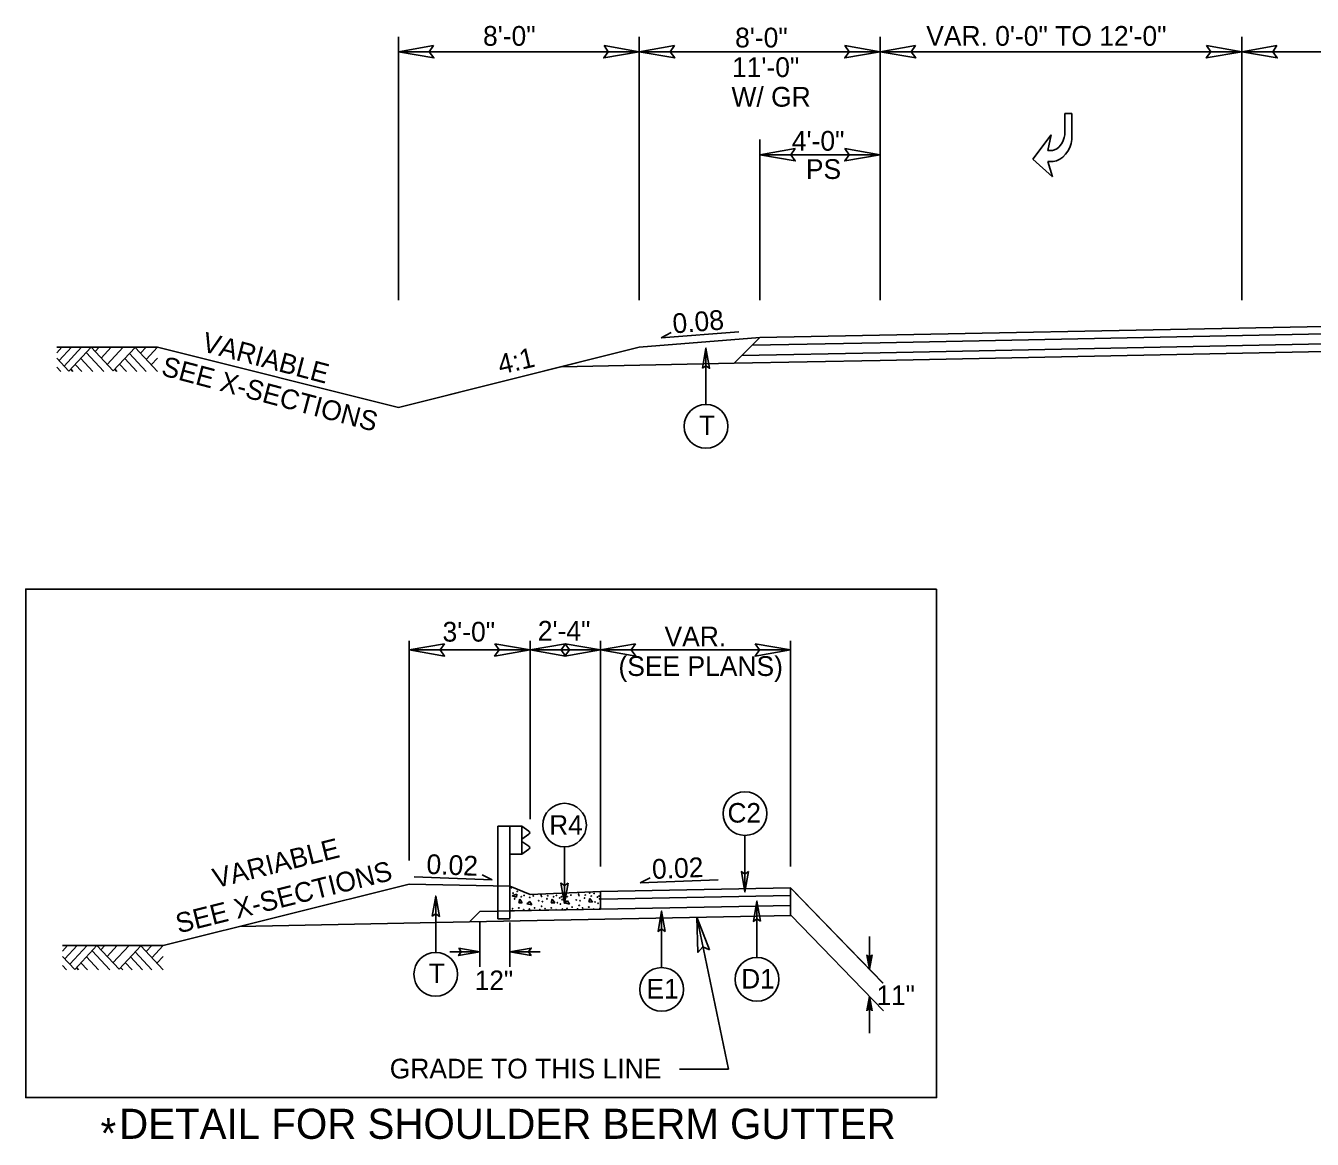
# Model space of a CAD drawing. Extents: x 1901582 to 1902252, y 193723 to 194156.
# Drawn here: x 1901985 to 1902027.72, y 194004.18 to 194041.16 of the extents above; entities that cross this region are included whole.
import ezdxf

# ---------------------------------------------------------------- set-up
doc = ezdxf.new("R2010")
doc.units = 0
for name, color, linetype in [('Default', 7, 'Continuous'), ('MARK BIKE LEFT ARROW CELL', 7, 'Continuous'), ('Old_Level_1', 7, 'Continuous'), ('Old_Level_11', 7, 'Continuous'), ('Old_Level_2', 7, 'Continuous'), ('Old_Level_20', 7, 'Continuous'), ('Prop Dimension Text', 7, 'Continuous'), ('Typical Curb CELL', 7, 'Continuous'), ('Typical Guardrail CELL', 7, 'Continuous'), ('Typical Pavement Slope Information CELL', 7, 'Continuous'), ('Typical Slope Point Local CELL', 7, 'Continuous'), ('Typical Terminator CELL', 7, 'Continuous')]:
    doc.layers.add(name, color=color, linetype=linetype)

# ---------------------------------------------------------------- blocks, each defined once
blk = doc.blocks.new('TERMINATOR')
at = {"layer": 'Typical Terminator CELL'}
blk.add_lwpolyline([(-0.469, 0.081), (0, 0), (-0.471, -0.083), (-0.411, 0)], close=True, dxfattribs=at)

msp = doc.modelspace()

# ---------------------------------------------------------------- linework, layer by layer
at = {"layer": 'Default'}
for p, q in [((1902000.082, 194009.909), (1902000.082, 194011.38)), ((1902001.082, 194009.909), (1902001.082, 194011.38)), ((1901999.082, 194010.409), (1902000.082, 194010.409)), ((1902001.082, 194010.409), (1902002.082, 194010.409))]:
    msp.add_line(p, q, dxfattribs=at)
at = {"layer": 'MARK BIKE LEFT ARROW CELL'}
for p, q in [((1902019.504, 194037.539), (1902019.504, 194038.245)), ((1902019.504, 194038.245), (1902019.735, 194038.245)), ((1902019.504, 194037.539), (1902019.504, 194038.245)), ((1902019.504, 194038.245), (1902019.735, 194038.245)), ((1902019.735, 194038.245), (1902019.735, 194037.385)), ((1902019.735, 194038.245), (1902019.735, 194037.385)), ((1902018.439, 194036.731), (1902019.055, 194037.539)), ((1902018.439, 194036.731), (1902019.055, 194037.539)), ((1902019.055, 194037.539), (1902018.939, 194037.02)), ((1902019.055, 194037.539), (1902018.939, 194037.02)), ((1902018.939, 194037.02), (1902019.093, 194037.02)), ((1902018.939, 194037.02), (1902019.093, 194037.02)), ((1902019.09, 194036.146), (1902018.439, 194036.731)), ((1902019.09, 194036.146), (1902018.439, 194036.731)), ((1902018.939, 194036.654), (1902019.09, 194036.146)), ((1902019.112, 194036.654), (1902018.939, 194036.654)), ((1902018.939, 194036.654), (1902019.09, 194036.146)), ((1902019.112, 194036.654), (1902018.939, 194036.654))]:
    msp.add_line(p, q, dxfattribs=at)
for centre, major_axis, ratio in [((1902019.158, 194037.475), (0.204, 0.44), 0.652763), ((1902019.158, 194037.475), (0.204, 0.44), 0.652763), ((1902019.177, 194037.321), (0.294, 0.632), 0.75825), ((1902019.177, 194037.321), (0.294, 0.632), 0.75825)]:
    msp.add_ellipse(centre, major_axis=major_axis, ratio=ratio, start_param=3.576577, end_param=5.147373, dxfattribs=at)
at = {"layer": 'Old_Level_1'}
for p, q in [((1901997.376, 194032.05), (1901997.376, 194040.8)), ((1902005.376, 194032.05), (1902005.376, 194040.8)), ((1902013.376, 194032.05), (1902013.376, 194040.8)), ((1902025.376, 194032.05), (1902025.376, 194040.8)), ((1902005.376, 194040.3), (1901997.376, 194040.3)), ((1902013.376, 194040.3), (1902005.376, 194040.3)), ((1902025.376, 194040.3), (1902013.376, 194040.3)), ((1902037.376, 194040.3), (1902025.376, 194040.3)), ((1902009.376, 194032.05), (1902009.376, 194037.381)), ((1902013.376, 194036.881), (1902009.376, 194036.881)), ((1902046.631, 194031.55), (1902009.376, 194030.805)), ((1902046.636, 194031.3), (1902013.376, 194030.635)), ((1902046.631, 194030.967), (1902013.376, 194030.301)), ((1902005.376, 194030.485), (1901999.054, 194028.904)), ((1902009.376, 194030.805), (1902005.376, 194030.485)), ((1902008.525, 194029.954), (1902009.376, 194030.805)), ((1902013.376, 194030.635), (1902009.12, 194030.55)), ((1902046.631, 194030.716), (1902013.376, 194030.051)), ((1902013.376, 194030.051), (1902008.525, 194029.954)), ((1902013.376, 194030.301), (1902008.78, 194030.21)), ((1902008.525, 194029.954), (1902002.795, 194029.84)), ((1901997.732, 194013.443), (1901997.732, 194020.738)), ((1902001.749, 194014.819), (1902001.749, 194020.738)), ((1902004.082, 194013.243), (1902004.082, 194020.738)), ((1902010.398, 194013.243), (1902010.398, 194020.738)), ((1902001.749, 194020.438), (1901997.732, 194020.438)), ((1901998.749, 194020.438), (1902001.749, 194020.438)), ((1902001.749, 194020.438), (1902004.082, 194020.438)), ((1902010.398, 194020.438), (1902004.082, 194020.438)), ((1902000.487, 194012.794), (1902000.158, 194012.968)), ((1901997.732, 194012.657), (1901989.568, 194010.616)), ((1901997.732, 194012.657), (1902001.082, 194012.59)), ((1901997.901, 194012.896), (1902000.487, 194012.794)), ((1902010.398, 194012.533), (1902004.082, 194012.406)), ((1902005.405, 194012.694), (1902005.734, 194012.867)), ((1902007.991, 194012.796), (1902005.405, 194012.694)), ((1902010.397, 194012.533), (1902013.466, 194009.363)), ((1902010.398, 194012.533), (1902010.398, 194011.616)), ((1902010.399, 194012.533), (1902013.467, 194009.363)), ((1902010.398, 194012.283), (1902004.082, 194012.156)), ((1902010.398, 194012.283), (1902004.088, 194012.156)), ((1902010.483, 194012.445), (1902013.466, 194009.363)), ((1902000.082, 194011.743), (1901999.742, 194011.403)), ((1902010.398, 194011.949), (1902000.082, 194011.743)), ((1901999.742, 194011.403), (1901992.105, 194011.25)), ((1902010.416, 194011.616), (1901999.742, 194011.403)), ((1902007.285, 194011.554), (1902008.34, 194006.508)), ((1902010.416, 194011.616), (1902013.484, 194008.447)), ((1902013.017, 194010.915), (1902013.017, 194009.827)), ((1902013.017, 194010.915), (1902013.017, 194009.827)), ((1902013.018, 194010.915), (1902013.018, 194009.827)), ((1902013.017, 194009.827), (1902012.932, 194010.304)), ((1902013.017, 194009.827), (1902012.933, 194010.304)), ((1902013.018, 194009.827), (1902012.934, 194010.304)), ((1902012.944, 194010.295), (1902013.017, 194009.827)), ((1902012.945, 194010.295), (1902013.017, 194009.827)), ((1902012.946, 194010.295), (1902013.018, 194009.827)), ((1902013.017, 194009.827), (1902012.957, 194010.286)), ((1902013.017, 194009.827), (1902012.958, 194010.286)), ((1902013.018, 194009.827), (1902012.959, 194010.286)), ((1902012.969, 194010.278), (1902013.017, 194009.827)), ((1902012.97, 194010.278), (1902013.017, 194009.827)), ((1902012.971, 194010.278), (1902013.018, 194009.827)), ((1902013.017, 194009.827), (1902012.981, 194010.269)), ((1902013.017, 194009.827), (1902012.982, 194010.269)), ((1902013.018, 194009.827), (1902012.983, 194010.269)), ((1902012.993, 194010.26), (1902013.017, 194009.827)), ((1902012.994, 194010.26), (1902013.017, 194009.827)), ((1902012.995, 194010.26), (1902013.018, 194009.827)), ((1902013.017, 194009.827), (1902013.005, 194010.251)), ((1902013.017, 194009.827), (1902013.006, 194010.251)), ((1902013.018, 194009.827), (1902013.007, 194010.251)), ((1902013.017, 194009.827), (1902013.102, 194010.304)), ((1902013.017, 194009.827), (1902013.101, 194010.304)), ((1902013.017, 194009.827), (1902013.09, 194010.295)), ((1902013.017, 194009.827), (1902013.089, 194010.295)), ((1902013.078, 194010.286), (1902013.017, 194009.827)), ((1902013.077, 194010.286), (1902013.017, 194009.827)), ((1902013.017, 194009.827), (1902013.066, 194010.278)), ((1902013.017, 194009.827), (1902013.065, 194010.278)), ((1902013.053, 194010.269), (1902013.017, 194009.827)), ((1902013.053, 194010.269), (1902013.017, 194009.827)), ((1902013.017, 194009.827), (1902013.041, 194010.26)), ((1902013.017, 194009.827), (1902013.041, 194010.26)), ((1902013.029, 194010.251), (1902013.017, 194009.827)), ((1902013.029, 194010.251), (1902013.017, 194009.827)), ((1902013.017, 194010.242), (1902013.017, 194009.827)), ((1902013.017, 194010.242), (1902013.017, 194009.827)), ((1902013.018, 194009.827), (1902013.103, 194010.304)), ((1902013.018, 194009.827), (1902013.091, 194010.295)), ((1902013.079, 194010.286), (1902013.018, 194009.827)), ((1902013.018, 194009.827), (1902013.067, 194010.278)), ((1902013.054, 194010.269), (1902013.018, 194009.827)), ((1902013.018, 194009.827), (1902013.042, 194010.26)), ((1902013.03, 194010.251), (1902013.018, 194009.827)), ((1902013.018, 194010.242), (1902013.018, 194009.827)), ((1902013.018, 194008.928), (1902012.934, 194008.45)), ((1902013.018, 194008.928), (1902012.946, 194008.46)), ((1902012.959, 194008.468), (1902013.018, 194008.928)), ((1902013.018, 194008.928), (1902012.971, 194008.478)), ((1902012.983, 194008.486), (1902013.018, 194008.928)), ((1902013.018, 194008.928), (1902012.995, 194008.494)), ((1902013.007, 194008.503), (1902013.018, 194008.928)), ((1902013.018, 194008.928), (1902013.103, 194008.45)), ((1902013.091, 194008.46), (1902013.018, 194008.928)), ((1902013.018, 194008.928), (1902013.079, 194008.468)), ((1902013.067, 194008.478), (1902013.018, 194008.928)), ((1902013.018, 194008.928), (1902013.054, 194008.486)), ((1902013.042, 194008.494), (1902013.018, 194008.928)), ((1902013.018, 194008.928), (1902013.03, 194008.503)), ((1902013.018, 194008.928), (1902013.018, 194007.702)), ((1902006.705, 194006.508), (1902008.34, 194006.508))]:
    msp.add_line(p, q, dxfattribs=at)
for points in [[(1901989.376, 194030.485), (1901986.034, 194030.485)], [(1901989.376, 194030.485), (1901997.376, 194028.485)], [(1902005.376, 194030.485), (1901997.376, 194028.485)], [(1901989.568, 194010.616), (1901986.226, 194010.616)]]:
    msp.add_lwpolyline(points, dxfattribs=at)
at = {"layer": 'Old_Level_11'}
for p, q in [((1901986.204, 194030.485), (1901986.034, 194030.302)), ((1901986.524, 194030.485), (1901986.11, 194030.041)), ((1901986.857, 194030.485), (1901986.277, 194029.862)), ((1901987.179, 194030.484), (1901986.438, 194029.688)), ((1901987.91, 194029.698), (1901987.179, 194030.484)), ((1901987.443, 194030.485), (1901987.31, 194030.342)), ((1901987.845, 194030.485), (1901987.512, 194030.126)), ((1901988.243, 194030.485), (1901987.71, 194029.912)), ((1901988.634, 194030.477), (1901987.91, 194029.698)), ((1901989.376, 194029.68), (1901988.634, 194030.477)), ((1901989.001, 194030.485), (1901988.814, 194030.284)), ((1901989.376, 194030.485), (1901989.001, 194030.082)), ((1902007.588, 194028.587), (1902007.588, 194030.461)), ((1901986.438, 194029.688), (1901986.034, 194030.123)), ((1901987.23, 194029.68), (1901986.83, 194030.109)), ((1901987.6, 194029.68), (1901987.014, 194030.308)), ((1901988.693, 194029.68), (1901988.292, 194030.109)), ((1901989.002, 194029.68), (1901988.448, 194030.276)), ((1901989.376, 194030.123), (1901989.17, 194029.901)), ((1901986.168, 194029.68), (1901986.034, 194029.823)), ((1901986.569, 194029.68), (1901986.5, 194029.754)), ((1901986.864, 194029.68), (1901986.647, 194029.913)), ((1901988.035, 194029.68), (1901987.964, 194029.756)), ((1901988.346, 194029.68), (1901988.119, 194029.923)), ((1902008.884, 194014.274), (1902008.884, 194012.4)), ((1902002.894, 194013.891), (1902002.894, 194012.017)), ((1901998.617, 194010.386), (1901998.617, 194012.26)), ((1902009.282, 194010.218), (1902009.282, 194012.092)), ((1902006.118, 194009.885), (1902006.118, 194011.76)), ((1901986.396, 194010.616), (1901986.226, 194010.433)), ((1901986.716, 194010.616), (1901986.302, 194010.172)), ((1901987.049, 194010.616), (1901986.469, 194009.993)), ((1901987.371, 194010.615), (1901986.63, 194009.819)), ((1901987.792, 194009.811), (1901987.206, 194010.439)), ((1901988.102, 194009.829), (1901987.371, 194010.615)), ((1901987.635, 194010.616), (1901987.502, 194010.473)), ((1901988.037, 194010.616), (1901987.704, 194010.257)), ((1901988.435, 194010.616), (1901987.902, 194010.043)), ((1901988.826, 194010.608), (1901988.102, 194009.829)), ((1901989.194, 194009.811), (1901988.64, 194010.407)), ((1901989.568, 194009.811), (1901988.826, 194010.608)), ((1901989.193, 194010.616), (1901989.006, 194010.415)), ((1901989.568, 194010.616), (1901989.193, 194010.213)), ((1901986.63, 194009.819), (1901986.226, 194010.254)), ((1901986.36, 194009.811), (1901986.226, 194009.954)), ((1901987.056, 194009.811), (1901986.839, 194010.044)), ((1901987.422, 194009.811), (1901987.022, 194010.24)), ((1901988.538, 194009.811), (1901988.311, 194010.054)), ((1901988.885, 194009.811), (1901988.484, 194010.24)), ((1901989.568, 194010.254), (1901989.362, 194010.032)), ((1901986.761, 194009.811), (1901986.692, 194009.885)), ((1901988.227, 194009.811), (1901988.156, 194009.887))]:
    msp.add_line(p, q, dxfattribs=at)
for points in [[(1902007.473, 194029.789), (1902007.588, 194030.461), (1902007.708, 194029.786), (1902007.588, 194029.871)], [(1902015.245, 194022.455), (1901985.005, 194022.455), (1901985.005, 194005.57), (1902015.245, 194005.57)], [(1902009, 194013.071), (1902008.884, 194012.4), (1902008.765, 194013.075), (1902008.884, 194012.989)], [(1902003.009, 194012.689), (1902002.894, 194012.017), (1902002.774, 194012.692), (1902002.894, 194012.606)], [(1901998.502, 194011.589), (1901998.617, 194012.26), (1901998.737, 194011.585), (1901998.617, 194011.671)], [(1902009.398, 194011.421), (1902009.282, 194012.092), (1902009.163, 194011.417), (1902009.282, 194011.503)], [(1902006.234, 194011.088), (1902006.118, 194011.76), (1902005.999, 194011.084), (1902006.118, 194011.17)]]:
    msp.add_lwpolyline(points, close=True, dxfattribs=at)
for centre in [(1902007.588, 194027.861), (1902008.884, 194014.999), (1902002.894, 194014.616), (1901998.617, 194009.661), (1902009.282, 194009.493), (1902006.118, 194009.16)]:
    msp.add_circle(centre, 0.725, dxfattribs=at)
at = {"layer": 'Typical Curb CELL'}
for p, q in [((1902001.749, 194012.313), (1902001.082, 194012.59)), ((1902001.082, 194012.59), (1902001.082, 194011.763)), ((1902001.156, 194012.27), (1902001.309, 194012.318)), ((1902001.294, 194012.227), (1902001.156, 194012.27)), ((1902001.309, 194012.318), (1902001.294, 194012.227)), ((1902001.404, 194012.154), (1902001.372, 194012.039)), ((1902001.492, 194012.036), (1902001.404, 194012.154)), ((1902001.739, 194012.082), (1902001.638, 194012.005)), ((1902001.804, 194011.969), (1902001.739, 194012.082)), ((1902004.082, 194012.406), (1902001.749, 194012.313)), ((1902002.48, 194012.154), (1902002.448, 194012.039)), ((1902002.568, 194012.036), (1902002.48, 194012.154)), ((1902002.988, 194012.107), (1902002.886, 194012.03)), ((1902003.053, 194011.994), (1902002.988, 194012.107)), ((1902003.728, 194012.179), (1902003.696, 194012.064)), ((1902003.696, 194012.064), (1902003.817, 194012.061)), ((1902003.817, 194012.061), (1902003.728, 194012.179)), ((1902004.082, 194012.406), (1902004.082, 194011.823)), ((1902001.082, 194011.766), (1902004.082, 194011.826)), ((1902001.372, 194012.039), (1902001.492, 194012.036)), ((1902001.638, 194012.005), (1902001.804, 194011.969)), ((1902002.448, 194012.039), (1902002.568, 194012.036)), ((1902002.886, 194012.03), (1902003.053, 194011.994))]:
    msp.add_line(p, q, dxfattribs=at)
for centre in [(1902001.128, 194012.538), (1902001.183, 194012.356), (1902001.233, 194012.168), (1902001.322, 194012.414), (1902001.454, 194012.235), (1902001.55, 194012.28), (1902001.736, 194012.213), (1902001.855, 194012.266), (1902002.035, 194012.105), (1902002.111, 194012.3), (1902002.13, 194012.25), (1902002.161, 194012.079), (1902002.308, 194012.168), (1902002.335, 194012.27), (1902002.53, 194012.235), (1902002.626, 194012.28), (1902002.736, 194012.199), (1902002.791, 194012.235), (1902002.81, 194012.138), (1902002.985, 194012.238), (1902003.104, 194012.291), (1902003.284, 194012.13), (1902003.36, 194012.325), (1902003.378, 194012.275), (1902003.41, 194012.104), (1902003.557, 194012.193), (1902003.583, 194012.295), (1902003.731, 194012.361), (1902003.778, 194012.26), (1902003.874, 194012.347), (1902003.908, 194012.063), (1902003.985, 194012.224), (1902004.04, 194012.259), (1902004.059, 194012.163), (1902001.171, 194011.841), (1902001.376, 194011.868), (1902001.537, 194011.803), (1902001.727, 194011.825), (1902001.897, 194011.868), (1902002.076, 194011.809), (1902002.13, 194011.924), (1902002.246, 194011.841), (1902002.451, 194011.868), (1902002.612, 194011.803), (1902002.659, 194012.038), (1902002.756, 194011.994), (1902002.822, 194011.83), (1902002.976, 194011.85), (1902003.146, 194011.893), (1902003.324, 194011.834), (1902003.379, 194011.949), (1902003.495, 194011.866), (1902003.7, 194011.893), (1902003.861, 194011.828), (1902004.005, 194012.019), (1902004.071, 194011.855)]:
    msp.add_circle(centre, 0.00802, dxfattribs=at)
at = {"layer": 'Typical Guardrail CELL'}
for p, q in [((1902001.082, 194014.578), (1902000.684, 194014.578)), ((1902000.684, 194014.578), (1902000.684, 194012.598)), ((1902001.082, 194014.578), (1902001.082, 194012.59)), ((1902001.082, 194014.578), (1902001.48, 194014.578)), ((1902001.48, 194014.578), (1902001.48, 194013.65)), ((1902001.48, 194014.578), (1902001.712, 194014.416)), ((1902001.48, 194014.152), (1902001.712, 194014.314)), ((1902001.48, 194014.114), (1902001.48, 194014.152)), ((1902001.48, 194014.114), (1902001.48, 194014.077)), ((1902001.48, 194014.077), (1902001.712, 194013.915)), ((1902001.48, 194013.65), (1902001.712, 194013.813)), ((1902001.082, 194013.65), (1902001.48, 194013.65)), ((1902000.684, 194012.598), (1902000.684, 194011.505)), ((1902001.082, 194012.59), (1902001.082, 194011.513)), ((1902001.082, 194011.505), (1902000.684, 194011.505))]:
    msp.add_line(p, q, dxfattribs=at)
for centre, start, end in [((1902001.676, 194014.365), 304.9888, 54.997), ((1902001.676, 194013.864), 304.9634, 54.9941)]:
    msp.add_arc(centre, 0.0621, start, end, dxfattribs=at)
at = {"layer": 'Typical Pavement Slope Information CELL'}
for p, q in [((1902008.685, 194031.001), (1902006.105, 194030.794)), ((1902006.105, 194030.794), (1902006.428, 194030.981))]:
    msp.add_line(p, q, dxfattribs=at)
at = {"layer": 'Typical Terminator CELL'}
for points in [[(1901998.547, 194040.502), (1901997.376, 194040.3), (1901998.554, 194040.092), (1901998.404, 194040.3)], [(1902004.204, 194040.502), (1902005.376, 194040.3), (1902004.197, 194040.092), (1902004.347, 194040.3)], [(1902006.547, 194040.502), (1902005.376, 194040.3), (1902006.554, 194040.092), (1902006.404, 194040.3)], [(1902012.204, 194040.502), (1902013.376, 194040.3), (1902012.197, 194040.092), (1902012.347, 194040.3)], [(1902014.547, 194040.502), (1902013.376, 194040.3), (1902014.554, 194040.092), (1902014.404, 194040.3)], [(1902024.204, 194040.502), (1902025.376, 194040.3), (1902024.197, 194040.092), (1902024.347, 194040.3)], [(1902026.547, 194040.502), (1902025.376, 194040.3), (1902026.554, 194040.092), (1902026.404, 194040.3)], [(1902010.547, 194037.083), (1902009.376, 194036.881), (1902010.554, 194036.673), (1902010.404, 194036.881)], [(1902012.204, 194037.083), (1902013.376, 194036.881), (1902012.197, 194036.673), (1902012.347, 194036.881)], [(1901998.903, 194020.64), (1901997.732, 194020.438), (1901998.91, 194020.229), (1901998.76, 194020.438)], [(1902000.577, 194020.64), (1902001.749, 194020.438), (1902000.571, 194020.229), (1902000.72, 194020.438)], [(1902002.921, 194020.64), (1902001.749, 194020.438), (1902002.927, 194020.229), (1902002.777, 194020.438)], [(1902002.91, 194020.64), (1902004.082, 194020.438), (1902002.904, 194020.229), (1902003.054, 194020.438)], [(1902005.254, 194020.64), (1902004.082, 194020.438), (1902005.26, 194020.229), (1902005.111, 194020.438)], [(1902009.226, 194020.64), (1902010.398, 194020.438), (1902009.22, 194020.229), (1902009.369, 194020.438)], [(1902007.71, 194010.478), (1902007.285, 194011.554), (1902007.321, 194010.39), (1902007.49, 194010.574)]]:
    msp.add_lwpolyline(points, close=True, dxfattribs=at)

# ---------------------------------------------------------------- block references
at = {"layer": 'Old_Level_1', "xscale": 1.5, "yscale": 1.5}
msp.add_blockref('TERMINATOR', (1902000.082, 194010.409), dxfattribs=at)
at = {"layer": 'Old_Level_1', "xscale": 1.5, "yscale": 1.5, "rotation": 180}
msp.add_blockref('TERMINATOR', (1902001.082, 194010.409), dxfattribs=at)

# ---------------------------------------------------------------- texts
at = {"layer": 'Old_Level_1'}
for s, p in [('8\'-0"', (1902000.187, 194040.498)), ('8\'-0"', (1902008.556, 194040.443)), ('VAR. 0\'-0" TO 12\'-0"', (1902014.901, 194040.498)), ('11\'-0"', (1902008.453, 194039.459)), ('W/ GR', (1902008.436, 194038.475)), ('4\'-0"', (1902010.44, 194037.013)), ('3\'-0"', (1901998.842, 194020.71)), ('2\'-4"', (1902002.006, 194020.742)), ('VAR.', (1902006.213, 194020.553)), ('(SEE PLANS)', (1902004.684, 194019.569)), ('GRADE TO THIS LINE', (1901997.091, 194006.202))]:
    msp.add_text(s, height=0.656, dxfattribs=at).set_placement(p)
for s, rotation, p in [('VARIABLE', 345.2456, (1901990.818, 194030.364)), ('SEE X-SECTIONS', 345.1369, (1901989.472, 194029.564)), ('VARIABLE', 14.0362, (1901991.31, 194012.517)), ('SEE X-SECTIONS', 14.0362, (1901990.079, 194011.017))]:
    msp.add_text(s, height=0.656, rotation=rotation, dxfattribs=at).set_placement(p)
at = {"layer": 'Old_Level_11'}
for s, p in [('*', (1901987.488, 194003.885)), ('DETAIL FOR SHOULDER BERM GUTTER ', (1901988.105, 194004.197))]:
    msp.add_text(s, height=1, dxfattribs=at).set_placement(p)
at = {"layer": 'Old_Level_2'}
for s, rotation, p in [('0.08', 4.5739, (1902006.505, 194030.943)), ('0.02', 357.7461, (1901998.3, 194012.997)), ('0.02', 2.2539, (1902005.81, 194012.827))]:
    msp.add_text(s, height=0.656, rotation=rotation, dxfattribs=at).set_placement(p)
at = {"layer": 'Old_Level_20'}
for s, height, p in [('T', 0.649, (1902007.361, 194027.568)), ('C2', 0.6491, (1902008.305, 194014.7)), ('R4', 0.6491, (1902002.386, 194014.297)), ('T', 0.649, (1901998.389, 194009.368)), ('12"', 0.6491, (1901999.914, 194009.137)), ('E1', 0.6491, (1902005.617, 194008.857)), ('D1', 0.6491, (1902008.761, 194009.189)), ('11"', 0.6491, (1902013.253, 194008.642))]:
    msp.add_text(s, height=height, dxfattribs=at).set_placement(p)
at = {"layer": 'Prop Dimension Text'}
msp.add_text('PS', height=0.656, dxfattribs=at).set_placement((1902010.906, 194036.075))
at = {"layer": 'Typical Slope Point Local CELL'}
msp.add_text('4:1', height=0.656, rotation=13.0197, dxfattribs=at).set_placement((1902000.764, 194029.577))

doc.saveas('drawing.dxf')
